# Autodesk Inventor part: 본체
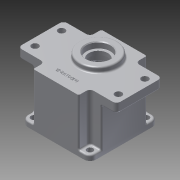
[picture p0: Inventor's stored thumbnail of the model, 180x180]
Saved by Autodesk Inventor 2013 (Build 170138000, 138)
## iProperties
Created: 2015-07
Part Number: 본체
Material: 알루미늄 6061
Document SubType Name: Modeling
Designer: user
Density: 2.71 g/cm^3
Mass: 705.341 g
Surface Area: 672.954 cm^2
Volume: 260.273 cm^3
Author: user
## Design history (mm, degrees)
sketch "스케치1"
  geometry: L1 (-30, 45)-(30, 45); L2 (30, 45)-(30, -45); L3 (30, -45)-(-30, -45); L4 (-30, -45)-(-30, 45); 3 further points
  constraints: 8 end point, 2 midpoint, 2 parallel, 1 horizontal, 1 horizontal alignment, 1 perpendicular, 1 vertical alignment
  dimensions: "d0" = 90 distance of L3.end L1.start; "d2" = 60 distance of L1.start L1.end
extrude "돌출1" new body sketch "스케치1" stored distance "d3" = 58; taper "d4" = 0 deg
sketch "스케치2"
  geometry: L1 (30, 45)-(-30, 45) reference; L2 (-30, 45)-(-30, -45) reference; L3 (-30, -45)-(30, -45) reference; L4 (30, -45)-(30, 45) reference; L5 (-65, 30)-(65, 30); L6 (65, 30)-(65, -30); L7 (65, -30)-(-65, -30); L8 (-65, -30)-(-65, 30); 3 further points
  constraints: 8 end point, 2 midpoint, 2 parallel, 1 horizontal, 1 horizontal alignment, 1 perpendicular, 1 vertical alignment
  dimensions: "d5" = 130 distance of L5.start L5.end; "d7" = 60 distance of L5.end L6.end
extrude "돌출2" join sketch "스케치2" distance "d8" = 12; taper "d9" = 0 deg
sketch "스케치3"
  geometry: L1 (30, -29)-(-30, -29) reference; L2 (-30, -29)-(-30, 29) reference; L3 (-30, 29)-(-65, 29) reference; L4 (-65, 29)-(-65, 41) reference; L5 (-65, 41)-(65, 41) reference; L6 (65, 41)-(65, 29) reference; L7 (65, 29)-(30, 29) reference; L8 (30, 29)-(30, -29) reference; L9 (0, -29)-(-45, -29); L10 (-45, -29)-(-45, 32.5); L11 (-45, 32.5)-(0, 32.5); L12 (0, 32.5)-(0, -29); L13 (45, 32.5)-(0, 32.5); L14 (45, -29)-(45, 32.5); L15 (0, -29)-(45, -29); 1 further point
  constraints: 14 end point, 2 perpendicular, 2 symmetric about line, 1 midpoint, 1 parallel
  dimensions: "d10" = 45 distance of L9.start L9.end; "d11" = 45 distance of L10.end L11.end; "d12" = 3.5 distance between parallel lines of L11 L3
extrude "돌출3" join sketch "스케치3" stored distance "d13" = 60; taper "d14" = 0 deg
sketch "스케치4"
  geometry: L1 (-30, -30)-(-30, -45) reference; L2 (-30, -45)-(30, -45) reference; L3 (30, -45)-(30, -30) reference; L4 (45, -30)-(30, -30) reference; L5 (45, -30)-(45, 30) reference; L6 (30, 30)-(45, 30) reference; L7 (30, 30)-(30, 45) reference; L8 (30, 45)-(-30, 45) reference; L9 (-30, 45)-(-30, 30) reference; L10 (-45, 30)-(-30, 30) reference; L11 (-45, -30)-(-45, 30) reference; L12 (-30, -30)-(-45, -30) reference; L13 (-45, 45)-(45, 45); L14 (45, 45)-(45, -45); L15 (45, -45)-(-45, -45); L16 (-45, -45)-(-45, 45); 3 further points
  constraints: 8 end point, 2 midpoint, 2 parallel, 1 horizontal, 1 horizontal alignment, 1 perpendicular, 1 vertical alignment
  dimensions: "d15" = 90 distance of L13.start L13.end; "d17" = 90 distance of L15.end L13.start
extrude "돌출4" join sketch "스케치4" distance "d18" = 7; taper "d19" = 0 deg
sketch "스케치8"
  geometry: C1 r 39 at (0, 0); 1 further point
  constraints: 1 centre point, 1 coincident
  dimensions: "d20" = 78 diameter of C1
extrude "돌출5" cut sketch "스케치8" distance "d21" = 61; taper "d22" = 0 deg
sketch "스케치9"
  geometry: C1 r 39 at (0, 0) reference; C2 r 40 at (0, 0)
  constraints: 1 centre point, 1 coincident
  dimensions: "d23" = 80 diameter of C2
extrude "돌출6" cut sketch "스케치9" distance "d24" = 9; taper "d25" = 0 deg
sketch "스케치10"
  geometry: L1 (30, -45)-(30, -30) reference; L2 (0, 0)-(55, 0); L3 (55, 17.5)-(55, -17.5); 2 further points
  constraints: 4 end point, 2 coincident, 2 perpendicular, 1 midpoint
  dimensions: "d26" = 55 distance of L2.end L2.start; "d28" = 35 distance of L3.start L3.end
hole "구멍1" sketch "스케치10" at (55, 17.5), (55, -17.5) diameter "d29" = 9; stored, may be unused: countersink angle "d33" = 90 deg, drill point angle "d35" = 118 deg; dims "d30" = 6, "d31" = 4, "d32" = 2, "d34" = 12
fillet "모깎기4" dims "d39" = 8
fillet "모깎기5" dims "d40" = 5
sketch "스케치11"
  geometry: L1 (-32, 43)-(-32, 35) reference; L2 (-37, 43)-(-32, 43) reference; L3 (-43, 32)-(-43, 37) reference; L4 (-35, 32)-(-43, 32) reference; L5 (-43, -32)-(-35, -32) reference; L6 (-43, -37)-(-43, -32) reference; L7 (-32, -43)-(-37, -43) reference; L8 (-32, -35)-(-32, -43) reference; L9 (32, -43)-(32, -35) reference; L10 (37, -43)-(32, -43) reference; L11 (43, -32)-(43, -37) reference; L12 (35, -32)-(43, -32) reference; A1 r 6 centre (37, 37) between (43, 37) and (37, 43) reference; A2 r 3 centre (-35, 35) between (-35, 32) and (-32, 35) reference; A3 r 6 centre (-37, 37) between (-37, 43) and (-43, 37) reference; A4 r 3 centre (-35, -35) between (-32, -35) and (-35, -32) reference; A5 r 6 centre (-37, -37) between (-43, -37) and (-37, -43) reference; A6 r 3 centre (35, -35) between (35, -32) and (32, -35) reference; A7 r 6 centre (37, -37) between (37, -43) and (43, -37) reference; 5 further points
  constraints: 4 coincident
hole "구멍2" sketch "스케치11" at (-37, 37), (-37, -37), (37, -37), (37, 37) diameter "d41" = 8; stored, may be unused: countersink angle "d45" = 90 deg, drill point angle "d47" = 118 deg; dims "d42" = 6, "d43" = 4, "d44" = 2, "d46" = 20
sketch "스케치12"
  geometry: L1 (-40, -29)-(-45, -29) reference; L2 (-45, -29)-(-45, 41) reference; L3 (-45, 41)-(45, 41) reference; L4 (45, 41)-(45, -29) reference; L5 (45, -29)-(40, -29) reference; L6 (40, -29)-(40, -20) reference; L7 (40, -20)-(39, -20) reference; L8 (39, -20)-(39, 32) reference; L9 (39, 32)-(-39, 32) reference; L10 (-39, 32)-(-39, -20) reference; L11 (-39, -20)-(-40, -20) reference; L12 (-40, -20)-(-40, -29) reference; L13 (0, 0)-(0, 48); L14 (36, 41)-(36, 48); L15 (11, 0)-(11, 67); L16 (31.5, 25)-(31.5, 41); L17 (11, 48)-(36, 48); L18 (11, 25)-(31.5, 25); L19 (36, 41)-(31.5, 41)
  constraints: 14 end point, 5 parallel, 4 point on line, 2 perpendicular, 1 collinear
  dimensions: "d48" = 11 distance between parallel lines of L13 L15; "d52" = 7 distance between parallel lines of L3 L17; "d53" = 7 distance between parallel lines of L9 L18; "d54" = 50 diameter of L14 L15; "d55" = 41 diameter of L16 L15
revolve "회전1" sketch "스케치12" stored, may be unused: angle "d56" = 90 deg
sketch "스케치13"
  geometry: L1 (0, 0)-(0, 53.036); L2 (-20, 0)-(-20, 53.036); L3 (-40, -29)-(-45, -29) reference; L4 (-45, -29)-(-45, 41) reference; L5 (-45, 41)-(-14, 41) reference; L6 (-14, 41)-(-14, 48) reference; L7 (-14, 48)-(36, 48) reference; L8 (36, 48)-(36, 41) reference; L9 (36, 41)-(45, 41) reference; L10 (45, 41)-(45, -29) reference; L11 (45, -29)-(40, -29) reference; L12 (40, -29)-(40, -20) reference; L13 (40, -20)-(39, -20) reference; L14 (39, -20)-(39, 32) reference; L15 (39, 32)-(31.5, 32) reference; L16 (31.5, 32)-(31.5, 25) reference; L17 (31.5, 25)-(-9.5, 25) reference; L18 (-9.5, 25)-(-9.5, 32) reference; L19 (-9.5, 32)-(-39, 32) reference; L20 (-39, 32)-(-39, -20) reference; L21 (-39, -20)-(-40, -20) reference; L22 (-40, -20)-(-40, -29) reference; L23 (-34, 32)-(-20, 32); L24 (-9.5, 25)-(6, 25); L25 (-34, 25)-(-20, 25); L26 (-34, 32)-(-34, 25)
  constraints: 13 end point, 3 collinear, 2 point on line, 1 parallel, 1 perpendicular, 1 vertical
  dimensions: "d57" = 20 distance between parallel lines of L2 L1; "d61" = 0 distance between parallel lines of L23 L19; "d62" = 7 distance between parallel lines of L25 L19; "d63" = 28 diameter of L26 L2; "d64" = 21.03581 distance from line of L2.end L19; "d65" = 32 distance from line of L2.start L19
revolve "회전2" sketch "스케치13" stored, may be unused: angle "d66" = 90 deg
fillet "모깎기6" dims "d67" = 2
fillet "모깎기8" dims "d69" = 3
sketch "스케치14"
  geometry: A1 r 14 centre (0, -31) between (-10.493, -21.732) and (10.493, -21.732) reference; 1 further point
hole "구멍3" sketch "스케치14" at (0, -31) diameter "d70" = 19; stored, may be unused: countersink angle "d74" = 90 deg, drill point angle "d76" = 0 deg; dims "d71" = 6, "d72" = 22, "d73" = 7, "d75" = 8
fillet "모깎기9" dims "d77" = 2
fillet "모깎기10" dims "d78" = 0.3
chamfer "모따기1" distance "d79" = 1; stored, may be unused: second distance "d80" = 2, angle "d81" = 45 deg
sketch "스케치15"
  geometry: A1 r 20.5 centre (0, 0) between (11.115, -17.225) and (-11.115, -17.225) reference; 1 further point
hole "구멍4" sketch "스케치15" at (0, 0) diameter "d82" = 25; stored, may be unused: countersink angle "d86" = 90 deg, drill point angle "d88" = 0 deg; dims "d83" = 6, "d84" = 35, "d85" = 10, "d87" = 15
sketch "스케치16"
  geometry: C1 r 25 at (0, 0) reference; 1 further point
hole "구멍5" sketch "스케치16" at (0, 0) diameter "d89" = 25; stored, may be unused: countersink angle "d93" = 90 deg, drill point angle "d95" = 0 deg; dims "d90" = 6, "d91" = 32, "d92" = 8, "d94" = 13
fillet "모깎기11" dims "d96" = 0.3
chamfer "모따기2" distance "d97" = 1; stored, may be unused: second distance "d98" = 2, angle "d99" = 45 deg
sketch "스케치20"
  geometry: L1 (0, 0)-(24.749, 24.749); L2 (0, 0)-(35, 0); A1 r 39 centre (0, 0) between (32.777, 21.134) and (21.134, 32.777) reference; A2 r 4 centre (24.749, 24.749) between (21.809, 27.462) and (27.462, 21.809); A3 r 3.5 centre (29.836, 19.238) between (32.777, 21.134) and (27.412, 21.762); A4 r 3.5 centre (19.238, 29.836) between (21.762, 27.412) and (21.134, 32.777)
  constraints: 10 point on circle, 4 end point, 4 tangent, 3 centre point, 2 coincident, 1 equal length, 1 horizontal
  dimensions: "d112" = 35 distance of L1.start L1.end; "d113" = 45 deg angle of L2 L1; "d115" = 8 diameter of A2; "d116" = 7 diameter of A3; "d117" = 7 diameter of A4
extrude "돌출8" join sketch "스케치20" distance "d118" = 52; taper "d119" = 0 deg
fillet "모깎기12" dims "d123" = 2
fillet "모깎기13" dims "d124" = 2
fillet "모깎기14" dims "d125" = 2
sketch "스케치21"
  geometry: A1 r 4 centre (24.749, 24.749) between (21.809, 27.462) and (27.462, 21.809) reference; A2 r 4 centre (24.749, -24.749) between (27.462, -21.809) and (21.809, -27.462) reference; A3 r 4 centre (-24.749, -24.749) between (-21.809, -27.462) and (-27.462, -21.809) reference; A4 r 4 centre (-24.749, 24.749) between (-27.462, 21.809) and (-21.809, 27.462) reference
hole "구멍6" sketch "스케치21" at (-24.749, 24.749), (-24.749, -24.749), (24.749, -24.749), (24.749, 24.749) diameter "d126" = 3.459; stored, may be unused: countersink angle "d130" = 90 deg, drill point angle "d132" = 118 deg; dims "d127" = 12, "d128" = 32, "d129" = 8, "d131" = 15
sketch "스케치22"
  geometry: L1 (-30, -45)-(30, -45) reference; L2 (-65, 25)-(-65, -25) reference; L3 (0, -45)-(0, -30); 4 further points
  constraints: 2 end point, 1 coincident, 1 midpoint, 1 parallel, 1 other
  dimensions: "d133" = 15 distance of L3.start L3.end
feature "엠보싱1" sketch "스케치22" dims "d134" = 0.5, "d135" = 0
fillet "모깎기15" dims "d136" = 2
fillet "모깎기16" dims "d137" = 2
fillet "모깎기17" dims "d138" = 2
fillet "모깎기18" dims "d139" = 2
node "솔리드1"
mirror "대칭1"
pattern_circular "원형 패턴2" dims angle "d121" = 360 deg
node "투영된 루프1"
node "투영된 루프2"
node "투영된 루프3"
node "절단 모서리 투영1"
node "절단 모서리 투영3"
node "절단 모서리 투영4"
other parameters: "d59" = 28, "d60" = 7, "d105" = 7
